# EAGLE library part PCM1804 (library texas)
FULL DIFFERENTIAL ANALOG INPUT 24-BIT, 192-kHz STEREO A/D CONVERTER Auto generated by make-symbol-device-package-bsdl.ulp Rev. 29 Source: http://focus.ti.com/lit/ds/symlink/pcm1804.pdf
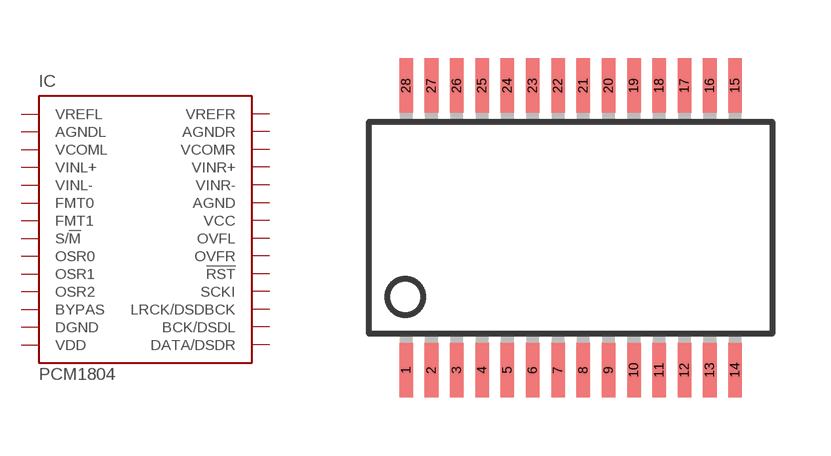
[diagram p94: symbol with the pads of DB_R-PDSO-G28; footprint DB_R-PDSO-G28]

Designator prefix IC

## PCM1804 (MF: TEXAS INSTRUMENT CONNECTORS; MPN: PCM1804DB; OC_FARNELL: 1197425; OC_NEWARK: 36K7583)  [DB_R-PDSO-G28]
1  VREFL  pwr
2  AGNDL  pwr
3  VCOML  pwr
4  VINL+  in
5  VINL-  in
6  FMT0  in
7  FMT1  in
8  S/!M  in
9  OSR0  in
10  OSR1  in
11  OSR2  in
12  BYPAS  in
13  DGND  pwr
14  VDD  pwr
15  DATA/DSDR  out
16  BCK/DSDL
17  LRCK/DSDBCK
18  SCKI  in
19  !RST  in
20  OVFR  out
21  OVFL  out
22  VCC  pwr
23  AGND  pwr
24  VINR-  in
25  VINR+  in
26  VCOMR  pwr
27  AGNDR  pwr
28  VREFR  pwr

## Footprint DB_R-PDSO-G28 (pad centres in mm)
DB (R-PDSO-G28) Source: http://focus.ti.com/lit/ds/symlink/ads1210.pdf
smd 0.348 x 1.397: 1 -4.225,-3.656; 2 -3.575,-3.656; 3 -2.925,-3.656; 4 -2.275,-3.656; 5 -1.625,-3.656; 6 -0.975,-3.656; 7 -0.325,-3.656; 8 0.325,-3.656; 9 0.975,-3.656; 10 1.625,-3.656; 11 2.275,-3.656; 12 2.925,-3.656; 13 3.575,-3.656; 14 4.225,-3.656; 15 4.225,3.656; 16 3.575,3.656; 17 2.925,3.656; 18 2.275,3.656; 19 1.625,3.656; 20 0.975,3.656; 21 0.325,3.656; 22 -0.325,3.656; 23 -0.975,3.656; 24 -1.625,3.656; 25 -2.275,3.656; 26 -2.925,3.656; 27 -3.575,3.656; 28 -4.225,3.656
